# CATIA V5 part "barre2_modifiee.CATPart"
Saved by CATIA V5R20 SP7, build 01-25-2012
Part number: barre2
Bounding box of the stored display mesh (mm): x 0 to 17, y -15.084 to 385.432, z -51.16 to 338.036
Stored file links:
  U:\Projet IAO\omeyer\Catia\barre2_modifiee.CATPart
  U:\Projet IAO\omeyer\Catia\Ass_748_skl.CATProduct
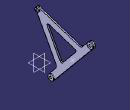
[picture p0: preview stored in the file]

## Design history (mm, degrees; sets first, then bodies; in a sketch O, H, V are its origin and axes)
Set1
  Plane1 "PlanRef": linked copy from another document
  DatumPoint1 "PointC": linked copy from another document
  Point1 "PointB": linked copy from another document
  DatumPoint2 "PointE": linked copy from another document
  Point2 "PointM": linked copy from another document
Body1 (main body)
  Sketch1 on Plane1, origin (0, 0, 0), H (0, 1, 0), V (0, 0, 1)
    point P1 (110.365, -44.0076)
    line L1 (110.365, -44.0076) -> (380.7878, 279.9608)
    arc A1 centre (365.4338, 292.7771) radius 20 from (380.7878, 279.9608) to (350.0798, 305.5933) ccw
    point P3 (365.4338, 292.7771)
    line L2 (350.0798, 305.5933) -> (310.0611, 257.6506)
    line L3 (277.742, 248.349) -> (4.5572, 337.2995)
    arc A2 centre (-0.0869, 323.0365) radius 15 from (4.5572, 337.2995) to (-13.2902, 315.9181) ccw
    point P6 (-0.0869, 323.0365)
    line L4 (-13.2902, 315.9181) -> (123.0516, 63.0288)
    line L5 (119.6758, 29.5676) -> (79.6571, -18.3751)
    arc A3 centre (95.0111, -31.1913) radius 20 from (79.6571, -18.3751) to (110.365, -44.0076) ccw
    point P9 (95.0111, -31.1913)
    arc A4 centre (287.0302, 276.875) radius 30 from (310.0611, 257.6506) to (277.742, 248.349) cw
    point P12 (287.0302, 276.875)
    arc A5 centre (96.6449, 48.792) radius 30 from (123.0516, 63.0288) to (119.6758, 29.5676) cw
    point P15 (96.6449, 48.792)
    reference projected point E1 (365.4338, 292.7771) from DatumPoint1
    reference projected point E2 (95.0111, -31.1913) from Point1
    reference projected point E3 (-0.0869, 323.0365) from DatumPoint2
    point P16 (110.365, -44.0076)
    circle A6 centre (365.4338, 292.7771) radius 7.5
    point P17 (365.4338, 292.7771)
    point P18 (-0.0869, 323.0365)
    circle A7 centre (-0.0869, 323.0365) radius 7.5
    circle A8 centre (95.0111, -31.1913) radius 7.5
    point P19 (95.0111, -31.1913)
    reference projected point E4 (365.4338, 292.7771) from DatumPoint1
    reference projected point E5 (95.0111, -31.1913) from Point1
    reference projected point E6 (-0.0869, 323.0365) from DatumPoint2
    line L6 (63.4102, 257.9413) -> (153.2861, 91.2377)
    line L7 (169.7653, 89.5752) -> (259.9716, 197.643)
    line L8 (255.3907, 213.5598) -> (75.3085, 272.1955)
    arc A9 centre (72.2124, 262.6869) radius 10 from (75.3085, 272.1955) to (63.4102, 257.9413) ccw
    arc A10 centre (252.2946, 204.0511) radius 10 from (255.3907, 213.5598) to (259.9716, 197.643) cw
    arc A11 centre (162.0884, 95.9833) radius 10 from (153.2861, 91.2377) to (169.7653, 89.5752) ccw
    radius A4 = 30
    radius A5 = 30
    radius A1 = 20
    radius A3 = 20
    radius A2 = 15
    distance P12 L1 = 70
    distance P15 L1 = 70
    distance P12 A1 = 100
    distance P15 A3 = 100
    radius A6 = 7.5
    radius A7 = 7.5
    radius A8 = 7.5
    distance L8 L3 = 40
    distance L6 L4 = 40
    distance L7 L1 = 40
    radius A9 = 10
    radius A10 = 10
    radius A11 = 10
    tangency: A1 L1, A2 L3, A3 L5, A1 L2, A4 L2, A4 L3, A5 L4, A5 L5, A2 L4, L1 A3, A9 L8, A9 L6, A10 L8, A10 L7, A11 L6, A11 L7
    coincidence: P3 E1, P9 E2, P6 E3, P1 P16, P17 E4, P19 E5, P18 E6
  Pad1: profile Sketch1, direction (1, 0, 0), length 10
  Sketch2 on end face of Pad1, origin (10, 0, 0), H (0, 1, 0), V (0, 0, 1)
    projected circle E1 centre (365.4338, 292.7771) radius 7.5 from edge [end face of Pad1 | face of Pad1 from Sketch1.A6]
    projected circle E2 centre (-0.0869, 323.0365) radius 7.5 from edge [end face of Pad1 | face of Pad1 from Sketch1.A7]
    projected circle E3 centre (95.0111, -31.1913) radius 7.5 from edge [end face of Pad1 | face of Pad1 from Sketch1.A8]
    circle A1 centre (95.0111, -31.1913) radius 19.0111
    point P1 (95.0111, -31.1913)
    circle A2 centre (365.4338, 292.7771) radius 19.575
    point P2 (365.4338, 292.7771)
    circle A3 centre (-0.0869, 323.0365) radius 14.2252
    point P3 (-0.0869, 323.0365)
    concentricity: P1 E3, P2 E1, P3 E2
  Pad2: profile Sketch2, direction (1, 0, 0), length 7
